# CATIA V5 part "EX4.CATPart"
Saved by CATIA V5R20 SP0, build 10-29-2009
Part number: EX4
Bounding box of the stored display mesh (mm): x -108 to 108, y 0 to 101.5, z 0 to 10
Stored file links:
  E:\Nouveau dossier\tarek\mécaniquee\Catia\TP 0\EX4.CATPart
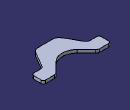
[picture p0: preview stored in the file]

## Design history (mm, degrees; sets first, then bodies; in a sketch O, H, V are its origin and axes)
Set1
  DatumSurface1 to DatumSurface24
Body1 (main body)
